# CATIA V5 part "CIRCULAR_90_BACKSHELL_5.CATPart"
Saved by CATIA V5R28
Part number: CIRCULAR_90_BACKSHELL_5
Revision: --A
Publications: "Logical Termination.1", "BCP", "BCPRPoint_generated(BCP)", "BCPPlane_generated(BCP)", "BaCP", "Face_generated(BaCP)", "Face_generated(BaCP).1", "MasterKeywayAxis", "Axis_generated(BaCP)"
Bounding box of the stored display mesh (mm): x 0 to 48.87, y -16.899 to 16.899, z -49.53 to 16.95
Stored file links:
  C:\Users\ajc8720\Documents\BOEING_WORK\0001-2CES\004-AP242\Boeing-Generic_Harness_R3\CIRCULAR_90_BACKSHELL_5.CATPart
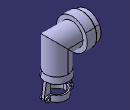
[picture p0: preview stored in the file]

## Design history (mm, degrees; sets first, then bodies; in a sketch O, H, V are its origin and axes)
Parameters
  PartNumber = "CIRCULAR_90_BACKSHELL_5"
AxisSystem1 "MasterKeywayAxis": origin (0, 0, 0), X (1, 0, 0), Y (0, 1, 0), Z (0, 0, 1)
Set1
  Point1: (33.528 {= Sketch2.distance(P3 V)}, 12.7, 0)
  Plane1: type 1Line1Pt, RefPoint Point1, Line Sketch2.L1
  Point2: type OnCurve, Support Sketch2.L4, Ratio 0.5
  Line1: type PtDir, RefPoint Point2, Direction (0, 1, 0), Start 0, End 5.08
  Point3: type OnCurve, Support Line1, Ratio 0.5
  Plane2: type 1Line1Pt, RefPoint Point3, Line Sketch2.L4
  Point4: type Center, Curve edge [face of Shaft1 from Sketch1.L5 | face of Shaft1 from Sketch1.L6]
  Plane3: type Tangent, Support face of Shaft1 from Sketch1.L5, RefPoint Point4
  Plane4: type OffsetPt, RefPlane Plane2, RefPoint Sketch2.P10
  Line2: type PtPt, FirstPoint vertex [face of Pad3 from Sketch5.L6 | face of Pad3 from Sketch5.L12 | end face of Pad3], SecondPoint vertex [face of Pad3 from Sketch5.L3 | face of Pad3 from Sketch5.L4 | start face of Pad3]
  Point5: type OnCurve, Support Line2, Ratio 0.5
  Plane5: type Tangent, Support face of Pad3 from Sketch5.L6, RefPoint Point5
Set2 "EGFOBody"
  Set3 "BCPOBody"
    Point6 "BCPRPoint": type Center, Curve edge [start face of Pad4 | face of Pad4 from Sketch6.A3]
    Plane6 "BCPPlane": type Tangent, Support start face of Pad4, RefPoint Point6
  Set4 "BaCPOBody"
    Point7 "BaCPRPoint": type Center, Curve edge [face of Shaft1 from Sketch1.L6 | face of Shaft1 from Sketch1.L7]
    Plane7 "BaCPCPlane": type Tangent, Support face of Shaft1 from Sketch1.L7, RefPoint Point7
    Line3 "BaCPCLine": type PtDir, RefPoint Point7, Direction (0, 1, 0), Start 0, End 5.08
Body1 (main body)
  Sketch1 on xy-plane, origin (0, 0, 0), H (1, 0, 0), V (0, 1, 0)
    line L1 (0, 12.5984) -> (0, 15.3416)
    line L2 (0, 15.3416) -> (4.7625, 15.3416)
    point P3 (4.7625, 15.3416)
    line L3 (4.7625, 15.3416) -> (6.3754, 16.9545)
    line L4 (6.3754, 16.9545) -> (16.764, 16.9545)
    line L5 (16.764, 16.9545) -> (16.764, 8.8646)
    line L6 (16.764, 8.8646) -> (7.747, 8.8646)
    line L7 (7.747, 8.8646) -> (7.747, 12.5984)
    line L8 (7.747, 12.5984) -> (0, 12.5984)
    axis line L9 (-2.2417, 0) -> (20.7737, 0)
    point P9 (-2.2417, 0)
    distance P3 L1 = 4.7625
    angle L3 L4 = 45
    distance L1 L7 = 7.747
    distance L1 L5 = 16.764
    distance L6 H = 8.8646
    distance L8 H = 12.5984
    distance L2 H = 15.3416
    distance L4 H = 16.9545
    vertical: L1 V, L5 V, L7 V
    horizontal: L2 H, L4 H, L6 H, L8 H, L9 H
    coincidence: L1 V, P9 H
  Shaft1: profile Sketch1, axis Sketch1.L9, angle 360
  Sketch2 on zx-plane, origin (0, 0, 0), H (-1, 0, 0), V (0, 0, 1)
    line L1 (-33.528, 0) -> (-49.3306, 15.8026)
    line L2 (-33.528, 0) -> (-36.5055, 0)
    point P3 (-33.528, 0)
    line L3 (-33.528, 0) -> (-33.528, -24.13)
    line L4 (-33.528, -24.13) -> (48.4208, -24.13)
    reference projected point E1 (-33.528, 0) from Point1
    point P7 (-33.528, -24.13)
    line L5 (-33.528, -30.48) -> (48.4208, -30.48)
    construction line L6 (-33.528, -24.13) -> (-33.528, -30.48)
    construction line L7 (48.4208, -24.13) -> (48.4208, -30.48)
    point P10 (-33.528, -30.48)
    point P11 (-33.528, 0)
    angle L1 V = 45
    distance P3 V = 33.528
    distance L4 E1 = 24.13
    angle L3 H = 90
    distance L4 L5 = 6.35
    horizontal: L2 H
    coincidence: L2 P3, L1 P3, L2 H, L4 P7, L3 P7, L3 P10, L5 P10, L1 P11, L3 P11
    perpendicularity: L4 L3, L6 L4, L6 L5, L7 L4, L7 L5
  Sketch3 on Plane3, origin (16.764, 0, 0), H (0, -1, 0), V (0, 0, 1)
    circle A1 centre (0, 0) radius 8.8646
    circle A2 centre (0, 0) radius 12.2936
    radius A1 = 8.8646
    radius A2 = 12.2936
  Pad1: profile Sketch3, direction (1, 0, 0), up to Plane1
  Sketch4 on Plane2, origin (-82.408, 0, -24.13), H (0, 1, 0), V (1, 0, 0)
    circle A1 centre (0, 115.936) radius 8.8646
    point P1 (0, 115.936)
    circle A2 centre (0, 115.936) radius 12.2936
    reference projected point E1 (0, 115.936) from Sketch2.P7
    radius A1 = 8.8646
    radius A2 = 12.2936
    coincidence: P1 V, P1 E1
  Pad2: profile Sketch4, direction (0, 0, 1), up to Plane1
  Sketch5 on zx-plane, origin (0, 0, 0), H (-1, 0, 0), V (0, 0, 1)
    point P1 (0, 0)
    construction line L1 (0, 0) -> (-33.528, 0)
    point P2 (-33.528, 0)
    construction line L2 (-33.528, 0) -> (-33.528, -30.48)
    point P3 (-33.528, -30.48)
    point P4 (-3.6257, -30.48)
    line L3 (-45.6946, -49.53) -> (-42.2656, -49.53)
    point P5 (-42.2656, -49.53)
    line L4 (-42.2656, -49.53) -> (-42.2656, -43.18)
    line L5 (-42.3926, -30.48) -> (-46.7011, -30.48)
    circle A1 centre (-45.6946, -46.355) radius 1.8256
    arc A2 centre (-45.6946, -46.355) radius 3.175 from (-45.6946, -49.53) to (-48.8396, -45.9194) cw
    point P7 (-45.6946, -49.53)
    point P8 (-48.8396, -45.9194)
    point P10 (-24.7904, -49.53)
    point P12 (-21.3614, -49.53)
    line L6 (-21.3614, -49.53) -> (-24.7904, -49.53)
    circle A3 centre (-21.3614, -46.355) radius 1.8256
    line L7 (-48.8396, -45.9194) -> (-46.7011, -30.48)
    point P13 (-48.8396, -45.9194)
    point P14 (-46.7011, -30.48)
    point P15 (-18.2164, -45.9194)
    point P16 (-21.3614, -49.53)
    arc A4 centre (-21.3614, -46.355) radius 3.175 from (-21.3614, -49.53) to (-18.2164, -45.9194) ccw
    point P18 (-20.3549, -30.48)
    point P19 (-18.2164, -45.9194)
    line L8 (-18.2164, -45.9194) -> (-20.3549, -30.48)
    construction line L9 (-45.8216, -24.13) -> (-52.8013, -74.5226)
    point P20 (-45.8216, -24.13)
    line L10 (-42.2656, -43.18) -> (-42.3926, -43.18)
    line L11 (-42.3926, -43.18) -> (-42.3926, -30.48)
    point P22 (-42.2656, -43.18)
    point P23 (-42.3926, -30.48)
    point P24 (-42.3926, -43.18)
    point P25 (-24.7904, -43.18)
    point P26 (-24.7904, -49.53)
    line L12 (-24.7904, -49.53) -> (-24.7904, -43.18)
    point P27 (-24.6634, -43.18)
    point P28 (-24.7904, -43.18)
    line L13 (-24.7904, -43.18) -> (-24.6634, -43.18)
    point P29 (-24.6634, -30.48)
    point P30 (-24.6634, -43.18)
    line L14 (-24.6634, -43.18) -> (-24.6634, -30.48)
    point P31 (-20.3549, -30.48)
    point P32 (-24.6634, -30.48)
    line L15 (-24.6634, -30.48) -> (-20.3549, -30.48)
    distance P1 P2 = 33.528
    angle L1 L2 = 90
    distance P3 P2 = 30.48
    distance L5 L3 = 19.05
    radius A1 = 1.8256
    radius A2 = 3.175
    distance L4 L2 = 8.7376
    distance A2 L2 = 15.3416
    distance P20 L2 = 12.2936 {= Sketch3.radius(A2)}
    distance P20 L5 = 6.35
    distance L10 L3 = 6.35
    distance L11 L2 = 8.8646
    horizontal: L1 H
    coincidence: P1 O, L5 P3, L7 P8, P8 A2, P4 L5, L7 L9
    tangency: A2 L3, A2 L7, L9 A2
    concentricity: A1 A2
    symmetry: P5 P10 L2, P7 P12 L2, L3 L6 L2, A1 A3 L2, P13 P15 L2, P7 P16 L2, A2 A4 L2, P14 P18 L2, P13 P19 L2, L7 L8 L2, P22 P25 L2, P5 P26 L2, L4 L12 L2, P24 P27 L2, P22 P28 L2, L10 L13 L2, P23 P29 L2, P24 P30 L2, L11 L14 L2, P14 P31 L2, P23 P32 L2, L5 L15 L2
    parallelism: L4 L2, L3 L5, L11 L4
    perpendicularity: L3 L2
  Pad3: profile Sketch5, direction (0, 1, 0), length 1.5875, opposite side length 1.5875
  Sketch6 on Plane5, origin (-156.6937, 0, -49.53), H (0, -1, 0), V (1, 0, 0)
    arc A1 centre (0, 190.2217) radius 8.897 from (1.6764, 198.9593) to (1.6764, 181.4841) cw
    point P1 (0, 190.2217)
    point P2 (1.6764, 198.9593)
    line L1 (1.6764, 198.9593) -> (1.6764, 205.5633)
    point P3 (1.6764, 205.5633)
    line L2 (1.6764, 174.8801) -> (1.6764, 181.4841)
    point P4 (1.6764, 174.8801)
    point P5 (1.6764, 181.4841)
    line L3 (3.2639, 174.8801) -> (3.2639, 180.2583)
    point P6 (3.2639, 174.8801)
    point P7 (3.2639, 180.2583)
    arc A2 centre (0, 190.2217) radius 10.4845 from (3.2639, 180.2583) to (3.2639, 200.1852) ccw
    point P8 (3.2639, 200.1852)
    line L4 (3.2639, 200.1852) -> (3.2639, 205.5633)
    point P9 (3.2639, 205.5633)
    line L5 (1.6764, 174.8801) -> (3.2639, 174.8801)
    line L6 (1.6764, 205.5633) -> (3.2639, 205.5633)
    construction line L7 (0, 190.2217) -> (0, 27.9514)
    point P11 (-1.6764, 198.9593)
    point P12 (-1.6764, 205.5633)
    point P13 (-1.6764, 174.8801)
    point P14 (-1.6764, 181.4841)
    point P15 (-3.2639, 174.8801)
    point P16 (-3.2639, 180.2583)
    point P17 (-3.2639, 200.1852)
    point P18 (-3.2639, 205.5633)
    point P19 (0, 190.2217)
    arc A3 centre (0, 190.2217) radius 8.897 from (-1.6764, 198.9593) to (-1.6764, 181.4841) ccw
    line L8 (-1.6764, 198.9593) -> (-1.6764, 205.5633)
    line L9 (-1.6764, 174.8801) -> (-1.6764, 181.4841)
    line L10 (-3.2639, 174.8801) -> (-3.2639, 180.2583)
    arc A4 centre (0, 190.2217) radius 10.4845 from (-3.2639, 180.2583) to (-3.2639, 200.1852) cw
    line L11 (-3.2639, 200.1852) -> (-3.2639, 205.5633)
    line L12 (-1.6764, 174.8801) -> (-3.2639, 174.8801)
    line L13 (-1.6764, 205.5633) -> (-3.2639, 205.5633)
    reference projected point E1 (0, 190.2217) from Point5
    distance L2 L3 = 1.5875
    distance L2 P1 = 1.6764
    distance A1 A2 H = 1.5875
    distance L5 P1 = 15.3416
    distance L6 P1 = 15.3416
    distance P5 P19 V = 8.7376
    vertical: L1 V, L2 V, L7 V
    coincidence: P4 L1, L2 L1, L3 L4, P19 E1
    concentricity: A2 A1
    horizontal: L5 H, L6 H
    symmetry: P2 P11 L7, P3 P12 L7, P4 P13 L7, P5 P14 L7, P6 P15 L7, P7 P16 L7, P8 P17 L7, P9 P18 L7, A1 A3 L7, L1 L8 L7, L2 L9 L7, L3 L10 L7, A2 A4 L7, L4 L11 L7, L5 L12 L7, L6 L13 L7
  Pad4: profile Sketch6, direction (0, 0, 1), length 6.35
  Fillet1: radius 3.175 {= deleted_StrainReleaseWidth /2}, on edge [start face of Pad4 | face of Pad4 from Sketch6.L13]; edge [face of Pad4 from Sketch6.L13 | end face of Pad4]; edge [start face of Pad4 | face of Pad4 from Sketch6.L6]; edge [face of Pad4 from Sketch6.L6 | end face of Pad4]; edge [start face of Pad4 | face of Pad4 from Sketch6.L12]; edge [start face of Pad4 | face of Pad4 from Sketch6.L5]; edge [face of Pad4 from Sketch6.L12 | end face of Pad4]; edge [face of Pad4 from Sketch6.L5 | end face of Pad4]
  Sketch7 on face of Pad4 from Sketch6.L11, origin (72.7908, 3.2639, -31.7287), H (1, 0, 0), V (0, 0, -1)
    point P1 (-27.0962, 14.6263)
    reference projected arc E1 centre (-27.0962, 14.6263) radius 3.175 from (-24.8511, 12.3812) to (-24.8511, 16.8713) ccw from edge [face of Pad4 from Sketch6.L11 | face of Fillet1]
    concentricity: P1 E1
  Hole1: placed by Sketch7, at (45.6946, 3.2639, -46.355) direction (0, -1, 0), diameter 3.175, up to face of Pad4 from Sketch6.L4
  Sketch8 on face of Pad4 from Sketch6.L10, origin (57.6407, 3.2639, -47.0401), H (1, 0, 0), V (0, 0, -1)
    point P1 (-36.2793, -0.6851)
    reference projected arc E1 centre (-36.2793, -0.6851) radius 3.175 from (-34.0342, 1.5599) to (-38.5243, 1.5599) ccw from edge [face of Pad4 from Sketch6.L10 | face of Fillet1]
    concentricity: P1 E1
  Hole2: placed by Sketch8, at (21.3614, 3.2639, -46.355) direction (0, -1, 0), diameter 3.175, up to face of Pad4 from Sketch6.L3
  Sketch9 on zx-plane, origin (0, 0, 0), H (-1, 0, 0), V (0, 0, 1)
    construction line L1 (-24.3125, 0) -> (-33.528, 0)
    point P1 (-24.3125, 0)
    point P2 (-33.528, 0)
    construction line L2 (-33.528, 0) -> (-33.528, -24.13)
    point P3 (-33.528, -24.13)
    construction line L3 (-33.528, -24.13) -> (-8.1419, -24.13)
    line L4 (-46.7011, -30.48) -> (-45.8216, -24.13)
    point P6 (-45.8216, -24.13)
    line L5 (-45.8216, -24.13) -> (-42.3926, -24.13)
    line L6 (-42.3926, -24.13) -> (-42.3926, -30.48)
    line L7 (-42.3926, -30.48) -> (-46.7011, -30.48)
    axis line L8 (-33.528, -24.13) -> (-33.528, -87.9579)
    reference projected point E1 (-46.7011, -30.48) from edge [face of Pad3 from Sketch5.L7 | face of Pad3 from Sketch5.L5]
    distance P2 V = 33.528
    angle L1 L2 = 90
    distance P2 P3 = 24.13
    distance P6 L2 = 12.2936 {= Sketch3.radius(A2)}
    distance L5 L7 = 6.35
    distance L6 L2 = 8.8646
    coincidence: P1 H, L5 L3, L4 E1
    horizontal: L1 H
    perpendicularity: L3 L2
    parallelism: L8 L2
  Shaft2: profile Sketch9, axis Sketch9.L8, angle 360
Body2 "Male Cherbourg - BaCP"
  Sketch10 "Sketch" on Plane7, origin (7.747, 0, 0), H (0, 1, 0), V (0, 0, 1)
    line L1 (-0.672, 0.762) -> (0.672, 0.762)
    point P1 (-0.672, 0.762)
    point P2 (0.672, 0.762)
    arc A1 centre (0, 0) radius 1.016 from (-1.016, 0) to (1.016, 0) ccw
    point P3 (0, 0)
    point P4 (-1.016, 0)
    point P5 (1.016, 0)
    reference projected point E1 (0, 0) from Point7
    arc A2 centre (0, 0) radius 1.016 from (1.016, 0) to (0.672, 0.762) ccw
    point P6 (0, 0)
    point P7 (1.016, 0)
    point P8 (0.672, 0.762)
    arc A3 centre (0, 0) radius 1.016 from (-0.672, 0.762) to (-1.016, 0) ccw
    point P9 (0, 0)
    point P10 (-0.672, 0.762)
    point P11 (-1.016, 0)
    reference projected point E2 (0, 0) from Point7
    reference projected point E3 (0, 0) from Point7
    length L1 = 1.344
    radius A1 = 1.016
    radius A3 = 1.016
    radius A2 = 1.016
    distance L1 P5 = 0.762
    distance P4 L1 = 0.762
    distance P7 L1 = 0.762
    distance P11 L1 = 0.762
    coincidence: P3 E1, P6 E2, P9 E3, P8 P2, P10 P1
    horizontal: L1 H
  Pad5: profile Sketch10, direction (1, 0, 0), length 0.508, opposite side up to Plane7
